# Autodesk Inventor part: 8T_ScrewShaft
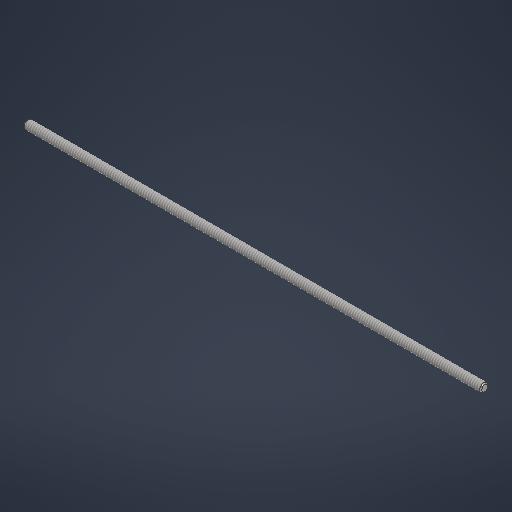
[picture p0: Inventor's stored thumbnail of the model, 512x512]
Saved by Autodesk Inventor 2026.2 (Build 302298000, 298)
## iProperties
Created: 2025-09
Part Number: 8T_ScrewShaft
Material: 스테인리스스틸
Document SubType Name: Modeling
Designer: work
Density: 8 g/cm^3
Appearance: 반연마
Author: work
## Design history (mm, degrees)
sketch "스케치1"
  geometry: C1 r 4 at (0, 0); 1 further point
  constraints: 1 centre point, 1 coincident
  dimensions: "d0" = 8 diameter of C1
extrude "돌출1" new body sketch "스케치1" distance "d1" = 430; taper "d2" = 0 deg
chamfer "모따기1" distance "d3" = 1; stored, may be unused: second distance "d4" = 2, angle "d5" = 45 deg
feature "스레드1" dims "d6" = 428, "d7" = 0
node "솔리드1"
feature "A9D066F2-1C7D-4E18-AEED-F7BC21143FA4" dims "d6" = 428, "d7" = 0
